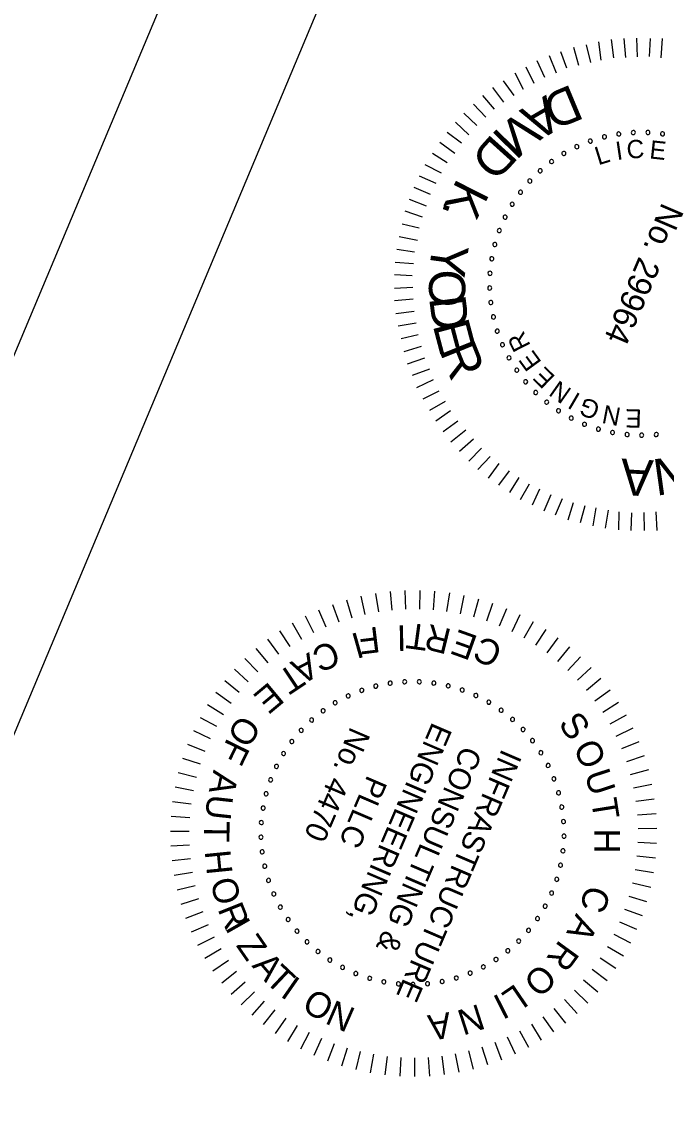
# Model space of a CAD drawing. Extents: x 1968564 to 1968711, y 796599 to 796794.
# Drawn here: x 1968580.42 to 1968589.2, y 796662.05 to 796676.76 of the extents above; entities that cross this region are included whole.
import ezdxf

# ---------------------------------------------------------------- set-up
doc = ezdxf.new("R2010")
doc.units = 0
for name, color, linetype in [('BR_BORDER LINES', 7, 'Continuous'), ('BR_TEXT', 7, 'Continuous'), ('Level 31', 7, 'Continuous')]:
    doc.layers.add(name, color=color, linetype=linetype)

msp = doc.modelspace()

# ---------------------------------------------------------------- linework, layer by layer
at = {"layer": 'BR_BORDER LINES'}
msp.add_line((1968618.549, 796758.212), (1968566.464, 796634.028), dxfattribs=at)
at = {"layer": 'BR_TEXT'}
for p, q in [((1968588.484, 796676.263), (1968588.452, 796676.511)), ((1968588.647, 796676.267), (1968588.626, 796676.523)), ((1968588.806, 796676.274), (1968588.796, 796676.528)), ((1968588.969, 796676.278), (1968588.982, 796676.527)), ((1968589.13, 796676.262), (1968589.148, 796676.523)), ((1968587.843, 796676.119), (1968587.761, 796676.345)), ((1968588.006, 796676.158), (1968587.939, 796676.403)), ((1968588.169, 796676.199), (1968588.112, 796676.441)), ((1968588.31, 796676.232), (1968588.279, 796676.481)), ((1968587.546, 796675.993), (1968587.442, 796676.22)), ((1968587.703, 796676.052), (1968587.606, 796676.288)), ((1968587.253, 796675.831), (1968587.138, 796676.052)), ((1968587.4, 796675.913), (1968587.29, 796676.136)), ((1968587.125, 796675.751), (1968586.982, 796675.947)), ((1968586.988, 796675.657), (1968586.838, 796675.856)), ((1968586.74, 796675.453), (1968586.572, 796675.63)), ((1968586.861, 796675.562), (1968586.698, 796675.748)), ((1968586.616, 796675.339), (1968586.441, 796675.507)), ((1968586.509, 796675.212), (1968586.33, 796675.386)), ((1968586.408, 796675.099), (1968586.212, 796675.243)), ((1968586.318, 796674.958), (1968586.114, 796675.109)), ((1968586.215, 796674.831), (1968586.015, 796674.957)), ((1968586.137, 796674.692), (1968585.916, 796674.806)), ((1968586.065, 796674.551), (1968585.838, 796674.649)), ((1968585.989, 796674.401), (1968585.765, 796674.497)), ((1968585.932, 796674.242), (1968585.702, 796674.333)), ((1968585.878, 796674.09), (1968585.644, 796674.172)), ((1968585.833, 796673.941), (1968585.602, 796673.995)), ((1968585.81, 796673.775), (1968585.561, 796673.822)), ((1968585.771, 796673.613), (1968585.529, 796673.65)), ((1968585.757, 796673.458), (1968585.508, 796673.472)), ((1968585.738, 796673.294), (1968585.496, 796673.305)), ((1968585.745, 796673.135), (1968585.496, 796673.122)), ((1968585.751, 796672.975), (1968585.497, 796672.95)), ((1968585.764, 796672.805), (1968585.515, 796672.774)), ((1968585.793, 796672.647), (1968585.548, 796672.607)), ((1968585.819, 796672.49), (1968585.586, 796672.434)), ((1968585.862, 796672.33), (1968585.625, 796672.256)), ((1968585.907, 796672.172), (1968585.669, 796672.088)), ((1968585.973, 796672.021), (1968585.738, 796671.935)), ((1968586.023, 796671.876), (1968585.797, 796671.768)), ((1968586.102, 796671.723), (1968585.884, 796671.615)), ((1968586.187, 796671.581), (1968585.975, 796671.46)), ((1968586.259, 796671.453), (1968586.06, 796671.311)), ((1968586.36, 796671.313), (1968586.159, 796671.168)), ((1968586.467, 796671.189), (1968586.266, 796671.025)), ((1968586.571, 796671.066), (1968586.381, 796670.901)), ((1968586.68, 796670.944), (1968586.511, 796670.77)), ((1968586.8, 796670.833), (1968586.63, 796670.655)), ((1968586.919, 796670.737), (1968586.771, 796670.539)), ((1968587.06, 796670.639), (1968586.915, 796670.44)), ((1968587.192, 796670.545), (1968587.064, 796670.342)), ((1968587.333, 796670.455), (1968587.208, 796670.243)), ((1968587.472, 796670.388), (1968587.371, 796670.17)), ((1968587.626, 796670.311), (1968587.529, 796670.087)), ((1968587.781, 796670.255), (1968587.686, 796670.034)), ((1968587.929, 796670.199), (1968587.858, 796669.964)), ((1968588.091, 796670.159), (1968588.026, 796669.93)), ((1968588.237, 796670.134), (1968588.199, 796669.889)), ((1968588.405, 796670.099), (1968588.364, 796669.855)), ((1968588.554, 796670.08), (1968588.545, 796669.834)), ((1968588.724, 796670.067), (1968588.713, 796669.825)), ((1968588.893, 796670.069), (1968588.895, 796669.822)), ((1968589.057, 796670.077), (1968589.067, 796669.823)), ((1968585.438, 796668.993), (1968585.463, 796668.74)), ((1968585.64, 796669.006), (1968585.649, 796668.752)), ((1968585.842, 796669.007), (1968585.836, 796668.753)), ((1968586.043, 796668.996), (1968586.022, 796668.742)), ((1968584.844, 796668.88), (1968584.915, 796668.635)), ((1968585.04, 796668.93), (1968585.095, 796668.681)), ((1968585.238, 796668.967), (1968585.278, 796668.716)), ((1968586.244, 796668.973), (1968586.207, 796668.721)), ((1968586.443, 796668.937), (1968586.39, 796668.688)), ((1968586.639, 796668.889), (1968586.571, 796668.643)), ((1968584.463, 796668.745), (1968584.563, 796668.511)), ((1968584.652, 796668.818), (1968584.737, 796668.578)), ((1968586.832, 796668.829), (1968586.749, 796668.588)), ((1968587.021, 796668.758), (1968586.924, 796668.523)), ((1968584.102, 796668.565), (1968584.23, 796668.344)), ((1968584.28, 796668.66), (1968584.394, 796668.433)), ((1968587.205, 796668.675), (1968587.094, 796668.446)), ((1968587.384, 796668.582), (1968587.259, 796668.36)), ((1968583.93, 796668.458), (1968584.071, 796668.246)), ((1968587.557, 796668.477), (1968587.418, 796668.263)), ((1968583.766, 796668.342), (1968583.919, 796668.139)), ((1968587.723, 796668.362), (1968587.572, 796668.157)), ((1968583.608, 796668.216), (1968583.774, 796668.022)), ((1968587.881, 796668.238), (1968587.718, 796668.042)), ((1968583.459, 796668.08), (1968583.636, 796667.897)), ((1968588.032, 796668.103), (1968587.858, 796667.918)), ((1968583.318, 796667.935), (1968583.506, 796667.763)), ((1968588.175, 796667.96), (1968587.989, 796667.786)), ((1968583.186, 796667.782), (1968583.384, 796667.622)), ((1968588.308, 796667.809), (1968588.112, 796667.646)), ((1968583.063, 796667.622), (1968583.271, 796667.474)), ((1968588.432, 796667.649), (1968588.227, 796667.499)), ((1968582.951, 796667.454), (1968583.167, 796667.319)), ((1968588.546, 796667.483), (1968588.332, 796667.345)), ((1968582.849, 796667.279), (1968583.073, 796667.158)), ((1968588.65, 796667.309), (1968588.428, 796667.185)), ((1968582.758, 796667.099), (1968582.989, 796666.992)), ((1968588.743, 796667.13), (1968588.513, 796667.02)), ((1968588.825, 796666.945), (1968588.589, 796666.849)), ((1968582.678, 796666.914), (1968582.915, 796666.82)), ((1968582.61, 796666.724), (1968582.852, 796666.645)), ((1968588.895, 796666.756), (1968588.654, 796666.674)), ((1968582.553, 796666.53), (1968582.8, 796666.466)), ((1968588.954, 796666.563), (1968588.708, 796666.496)), ((1968589, 796666.366), (1968588.751, 796666.315)), ((1968582.509, 796666.333), (1968582.759, 796666.284)), ((1968582.476, 796666.134), (1968582.728, 796666.1)), ((1968589.035, 796666.167), (1968588.783, 796666.131)), ((1968582.455, 796665.933), (1968582.709, 796665.915)), ((1968589.058, 796665.967), (1968588.804, 796665.946)), ((1968589.068, 796665.765), (1968588.813, 796665.76)), ((1968582.447, 796665.731), (1968582.702, 796665.729)), ((1968582.451, 796665.529), (1968582.706, 796665.542)), ((1968589.066, 796665.563), (1968588.811, 796665.573)), ((1968582.468, 796665.328), (1968582.721, 796665.357)), ((1968589.052, 796665.362), (1968588.798, 796665.387)), ((1968582.496, 796665.128), (1968582.747, 796665.172)), ((1968589.025, 796665.162), (1968588.774, 796665.203)), ((1968588.986, 796664.963), (1968588.738, 796665.02)), ((1968582.537, 796664.93), (1968582.785, 796664.99)), ((1968582.59, 796664.735), (1968582.834, 796664.81)), ((1968588.935, 796664.768), (1968588.691, 796664.839)), ((1968582.654, 796664.544), (1968582.893, 796664.633)), ((1968588.873, 796664.576), (1968588.633, 796664.662)), ((1968582.731, 796664.357), (1968582.963, 796664.46)), ((1968588.799, 796664.388), (1968588.565, 796664.489)), ((1968582.818, 796664.175), (1968583.044, 796664.292)), ((1968588.713, 796664.205), (1968588.486, 796664.32)), ((1968588.617, 796664.028), (1968588.397, 796664.156)), ((1968582.916, 796663.998), (1968583.135, 796664.129)), ((1968588.51, 796663.857), (1968588.298, 796663.998)), ((1968583.025, 796663.828), (1968583.235, 796663.972)), ((1968588.392, 796663.692), (1968588.189, 796663.846)), ((1968583.144, 796663.665), (1968583.345, 796663.822)), ((1968588.265, 796663.535), (1968588.072, 796663.702)), ((1968583.273, 796663.51), (1968583.464, 796663.678)), ((1968588.129, 796663.387), (1968587.946, 796663.564)), ((1968583.411, 796663.362), (1968583.591, 796663.542)), ((1968583.558, 796663.224), (1968583.727, 796663.414)), ((1968587.983, 796663.246), (1968587.812, 796663.435)), ((1968583.713, 796663.094), (1968583.87, 796663.295)), ((1968587.83, 796663.115), (1968587.67, 796663.314)), ((1968583.875, 796662.974), (1968584.02, 796663.184)), ((1968587.668, 796662.994), (1968587.521, 796663.202)), ((1968584.045, 796662.864), (1968584.176, 796663.083)), ((1968584.221, 796662.765), (1968584.339, 796662.991)), ((1968587.325, 796662.781), (1968587.204, 796663.005)), ((1968587.5, 796662.882), (1968587.366, 796663.099)), ((1968584.402, 796662.677), (1968584.506, 796662.91)), ((1968584.589, 796662.6), (1968584.678, 796662.838)), ((1968586.959, 796662.612), (1968586.866, 796662.849)), ((1968587.145, 796662.691), (1968587.038, 796662.922)), ((1968584.78, 796662.535), (1968584.855, 796662.778)), ((1968584.974, 796662.481), (1968585.034, 796662.728)), ((1968585.172, 796662.439), (1968585.217, 796662.69)), ((1968586.178, 796662.414), (1968586.145, 796662.666)), ((1968586.377, 796662.445), (1968586.329, 796662.695)), ((1968586.574, 796662.489), (1968586.511, 796662.736)), ((1968586.768, 796662.545), (1968586.69, 796662.787)), ((1968585.372, 796662.409), (1968585.401, 796662.662)), ((1968585.573, 796662.392), (1968585.587, 796662.646)), ((1968585.775, 796662.387), (1968585.773, 796662.641)), ((1968585.977, 796662.394), (1968585.96, 796662.648))]:
    msp.add_line(p, q, dxfattribs=at)
for centre, start, end in [((1968588.355, 796675.186), 14.1575, 194.1575), ((1968588.355, 796675.186), 194.1575, 14.1575), ((1968588.55, 796675.225), 8.619, 188.619), ((1968588.55, 796675.225), 188.619, 8.619), ((1968588.749, 796675.244), 3.0805, 183.0805), ((1968588.749, 796675.244), 183.0805, 3.0805), ((1968588.948, 796675.245), 357.5421, 177.5421), ((1968588.948, 796675.245), 177.5421, 357.5421), ((1968589.147, 796675.227), 352.0036, 172.0036), ((1968589.147, 796675.227), 172.0036, 352.0036), ((1968587.98, 796675.052), 25.2344, 205.2344), ((1968587.98, 796675.052), 205.2344, 25.2344), ((1968588.164, 796675.128), 19.6959, 199.6959), ((1968588.164, 796675.128), 199.6959, 19.6959), ((1968587.637, 796674.849), 36.3113, 216.3113), ((1968587.804, 796674.959), 30.7728, 210.7728), ((1968587.804, 796674.959), 210.7728, 30.7728), ((1968587.482, 796674.724), 41.8498, 221.8498), ((1968587.482, 796674.724), 221.8498, 41.8498), ((1968587.637, 796674.849), 216.3113, 36.3113), ((1968587.34, 796674.584), 47.3882, 227.3882), ((1968587.34, 796674.584), 227.3882, 47.3882), ((1968587.212, 796674.431), 52.9267, 232.9267), ((1968587.212, 796674.431), 232.9267, 52.9267), ((1968587.1, 796674.267), 58.4652, 238.4652), ((1968587.1, 796674.267), 238.4652, 58.4652), ((1968587.003, 796674.092), 64.0036, 244.0036), ((1968587.003, 796674.092), 244.0036, 64.0036), ((1968586.924, 796673.909), 69.5421, 249.5421), ((1968586.924, 796673.909), 249.5421, 69.5421), ((1968586.863, 796673.719), 75.0805, 255.0805), ((1968586.863, 796673.719), 255.0805, 75.0805), ((1968586.821, 796673.525), 80.619, 260.619), ((1968586.821, 796673.525), 260.619, 80.619), ((1968586.798, 796673.327), 86.1575, 266.1575), ((1968586.798, 796673.327), 266.1575, 86.1575), ((1968586.794, 796673.127), 91.6959, 271.6959), ((1968586.794, 796673.127), 271.6959, 91.6959), ((1968586.809, 796672.929), 97.2344, 277.2344), ((1968586.809, 796672.929), 277.2344, 97.2344), ((1968586.843, 796672.732), 102.7728, 282.7728), ((1968586.843, 796672.732), 282.7728, 102.7728), ((1968586.896, 796672.54), 108.3113, 288.3113), ((1968586.896, 796672.54), 288.3113, 108.3113), ((1968586.967, 796672.354), 113.8498, 293.8498), ((1968586.967, 796672.354), 293.8498, 113.8498), ((1968587.056, 796672.176), 119.3882, 299.3882), ((1968587.056, 796672.176), 299.3882, 119.3882), ((1968587.162, 796672.007), 124.9267, 304.9267), ((1968587.162, 796672.007), 304.9267, 124.9267), ((1968587.283, 796671.849), 130.4652, 310.4652), ((1968587.283, 796671.849), 310.4652, 130.4652), ((1968587.42, 796671.703), 136.0036, 316.0036), ((1968587.42, 796671.703), 316.0036, 136.0036), ((1968587.569, 796671.572), 141.5421, 321.5421), ((1968587.569, 796671.572), 321.5421, 141.5421), ((1968587.731, 796671.455), 147.0805, 327.0805), ((1968587.731, 796671.455), 327.0805, 147.0805), ((1968587.903, 796671.355), 152.619, 332.619), ((1968587.903, 796671.355), 332.619, 152.619), ((1968588.084, 796671.271), 158.1575, 338.1575), ((1968588.084, 796671.271), 338.1575, 158.1575), ((1968588.273, 796671.206), 163.6959, 343.6959), ((1968588.273, 796671.206), 343.6959, 163.6959), ((1968588.466, 796671.159), 169.2344, 349.2344), ((1968588.466, 796671.159), 349.2344, 169.2344), ((1968588.664, 796671.131), 174.7728, 354.7728), ((1968588.664, 796671.131), 354.7728, 174.7728), ((1968588.863, 796671.122), 0.3113, 180.3113), ((1968588.863, 796671.122), 180.3113, 0.3113), ((1968589.062, 796671.132), 5.8498, 185.8498), ((1968589.062, 796671.132), 185.8498, 5.8498), ((1968585.051, 796667.647), 19.6959, 199.6959), ((1968585.242, 796667.705), 14.1575, 194.1575), ((1968585.242, 796667.705), 194.1575, 14.1575), ((1968585.437, 796667.744), 8.619, 188.619), ((1968585.437, 796667.744), 188.619, 8.619), ((1968585.635, 796667.764), 3.0805, 183.0805), ((1968585.635, 796667.764), 183.0805, 3.0805), ((1968585.835, 796667.764), 357.5421, 177.5421), ((1968585.835, 796667.764), 177.5421, 357.5421), ((1968586.033, 796667.746), 172.0036, 352.0036), ((1968586.033, 796667.746), 352.0036, 172.0036), ((1968586.229, 796667.708), 166.4652, 346.4652), ((1968586.229, 796667.708), 346.4652, 166.4652), ((1968586.42, 796667.652), 340.9267, 160.9267), ((1968584.867, 796667.571), 25.2344, 205.2344), ((1968584.867, 796667.571), 205.2344, 25.2344), ((1968585.051, 796667.647), 199.6959, 19.6959), ((1968586.42, 796667.652), 160.9267, 340.9267), ((1968586.605, 796667.577), 155.3882, 335.3882), ((1968586.605, 796667.577), 335.3882, 155.3882), ((1968584.524, 796667.368), 36.3113, 216.3113), ((1968584.524, 796667.368), 216.3113, 36.3113), ((1968584.69, 796667.478), 30.7728, 210.7728), ((1968584.69, 796667.478), 210.7728, 30.7728), ((1968586.782, 796667.485), 149.8498, 329.8498), ((1968586.782, 796667.485), 329.8498, 149.8498), ((1968586.949, 796667.377), 144.3113, 324.3113), ((1968586.949, 796667.377), 324.3113, 144.3113), ((1968584.369, 796667.243), 41.8498, 221.8498), ((1968584.369, 796667.243), 221.8498, 41.8498), ((1968587.105, 796667.252), 138.7728, 318.7728), ((1968587.105, 796667.252), 318.7728, 138.7728), ((1968584.227, 796667.103), 47.3882, 227.3882), ((1968584.227, 796667.103), 227.3882, 47.3882), ((1968587.248, 796667.114), 133.2344, 313.2344), ((1968587.248, 796667.114), 313.2344, 133.2344), ((1968584.099, 796666.95), 52.9267, 232.9267), ((1968584.099, 796666.95), 232.9267, 52.9267), ((1968587.377, 796666.962), 127.6959, 307.6959), ((1968587.377, 796666.962), 307.6959, 127.6959), ((1968583.986, 796666.786), 58.4652, 238.4652), ((1968583.986, 796666.786), 238.4652, 58.4652), ((1968587.491, 796666.798), 122.1575, 302.1575), ((1968587.491, 796666.798), 302.1575, 122.1575), ((1968583.89, 796666.611), 64.0036, 244.0036), ((1968587.588, 796666.624), 116.619, 296.619), ((1968587.588, 796666.624), 296.619, 116.619), ((1968583.89, 796666.611), 244.0036, 64.0036), ((1968583.811, 796666.428), 69.5421, 249.5421), ((1968583.811, 796666.428), 249.5421, 69.5421), ((1968587.668, 796666.442), 111.0805, 291.0805), ((1968587.668, 796666.442), 291.0805, 111.0805), ((1968583.75, 796666.239), 75.0805, 255.0805), ((1968583.75, 796666.239), 255.0805, 75.0805), ((1968587.731, 796666.252), 105.5421, 285.5421), ((1968587.731, 796666.252), 285.5421, 105.5421), ((1968583.708, 796666.044), 80.619, 260.619), ((1968583.708, 796666.044), 260.619, 80.619), ((1968587.774, 796666.058), 100.0036, 280.0036), ((1968587.774, 796666.058), 280.0036, 100.0036), ((1968583.684, 796665.846), 86.1575, 266.1575), ((1968583.684, 796665.846), 266.1575, 86.1575), ((1968587.799, 796665.86), 94.4652, 274.4652), ((1968587.799, 796665.86), 274.4652, 94.4652), ((1968583.68, 796665.647), 91.6959, 271.6959), ((1968583.68, 796665.647), 271.6959, 91.6959), ((1968587.805, 796665.661), 88.9267, 268.9267), ((1968587.805, 796665.661), 268.9267, 88.9267), ((1968583.695, 796665.448), 97.2344, 277.2344), ((1968583.695, 796665.448), 277.2344, 97.2344), ((1968587.791, 796665.462), 83.3882, 263.3882), ((1968587.791, 796665.462), 263.3882, 83.3882), ((1968583.73, 796665.251), 102.7728, 282.7728), ((1968583.73, 796665.251), 282.7728, 102.7728), ((1968587.758, 796665.265), 77.8498, 257.8498), ((1968587.758, 796665.265), 257.8498, 77.8498), ((1968583.783, 796665.059), 108.3113, 288.3113), ((1968583.783, 796665.059), 288.3113, 108.3113), ((1968587.706, 796665.073), 72.3113, 252.3113), ((1968587.706, 796665.073), 252.3113, 72.3113), ((1968583.854, 796664.873), 113.8498, 293.8498), ((1968583.854, 796664.873), 293.8498, 113.8498), ((1968587.636, 796664.886), 66.7728, 246.7728), ((1968587.636, 796664.886), 246.7728, 66.7728), ((1968587.549, 796664.707), 61.2344, 241.2344), ((1968587.549, 796664.707), 241.2344, 61.2344), ((1968583.943, 796664.695), 119.3882, 299.3882), ((1968583.943, 796664.695), 299.3882, 119.3882), ((1968584.049, 796664.526), 124.9267, 304.9267), ((1968584.049, 796664.526), 304.9267, 124.9267), ((1968587.444, 796664.538), 55.6959, 235.6959), ((1968587.444, 796664.538), 235.6959, 55.6959), ((1968584.17, 796664.368), 130.4652, 310.4652), ((1968584.17, 796664.368), 310.4652, 130.4652), ((1968587.323, 796664.379), 50.1575, 230.1575), ((1968587.323, 796664.379), 230.1575, 50.1575), ((1968584.306, 796664.222), 136.0036, 316.0036), ((1968584.306, 796664.222), 316.0036, 136.0036), ((1968587.188, 796664.232), 44.619, 224.619), ((1968587.188, 796664.232), 224.619, 44.619), ((1968584.456, 796664.091), 141.5421, 321.5421), ((1968584.456, 796664.091), 321.5421, 141.5421), ((1968584.618, 796663.974), 327.0805, 147.0805), ((1968586.879, 796663.982), 33.5421, 213.5421), ((1968586.879, 796663.982), 213.5421, 33.5421), ((1968587.04, 796664.1), 39.0805, 219.0805), ((1968587.04, 796664.1), 219.0805, 39.0805), ((1968584.618, 796663.974), 147.0805, 327.0805), ((1968584.79, 796663.874), 152.619, 332.619), ((1968584.79, 796663.874), 332.619, 152.619), ((1968586.707, 796663.88), 28.0036, 208.0036), ((1968586.707, 796663.88), 208.0036, 28.0036), ((1968584.971, 796663.79), 158.1575, 338.1575), ((1968584.971, 796663.79), 338.1575, 158.1575), ((1968585.159, 796663.725), 163.6959, 343.6959), ((1968585.159, 796663.725), 343.6959, 163.6959), ((1968585.353, 796663.678), 349.2344, 169.2344), ((1968586.146, 796663.681), 11.3882, 191.3882), ((1968586.339, 796663.729), 16.9267, 196.9267), ((1968586.339, 796663.729), 196.9267, 16.9267), ((1968586.527, 796663.796), 22.4652, 202.4652), ((1968586.527, 796663.796), 202.4652, 22.4652), ((1968585.353, 796663.678), 169.2344, 349.2344), ((1968585.55, 796663.65), 354.7728, 174.7728), ((1968585.55, 796663.65), 174.7728, 354.7728), ((1968585.749, 796663.641), 0.3113, 180.3113), ((1968585.749, 796663.641), 180.3113, 0.3113), ((1968585.948, 796663.651), 5.8498, 185.8498), ((1968585.948, 796663.651), 185.8498, 5.8498), ((1968586.146, 796663.681), 191.3882, 11.3882)]:
    msp.add_arc(centre, 0.028, start, end, dxfattribs=at)
at = {"layer": 'Level 31'}
msp.add_lwpolyline([(1968619.541, 796765.748), (1968563.846, 796632.955), (1968644.997, 796598.919), (1968700.693, 796731.712)], close=True, dxfattribs=at)

# ---------------------------------------------------------------- texts
at = {"layer": 'BR_TEXT'}
for s, height, rotation, p in [('A', 0.494, 210.0837, (1968587.565, 796675.761)), ('D', 0.494, 202.6513, (1968587.91, 796675.906)), ('V', 0.494, 217.7639, (1968587.231, 796675.567)), ('D', 0.494, 228.0455, (1968586.83, 796675.24)), ('I', 0.494, 225.4441, (1968586.926, 796675.33)), ('L', 0.249, 17.2055, (1968588.272, 796674.797)), ('I', 0.249, 8.3471, (1968588.527, 796674.867)), ('C', 0.249, 3.6726, (1968588.665, 796674.887)), ('E', 0.249, 353.7815, (1968588.961, 796674.893)), ('K', 0.494, 243.344, (1968586.357, 796674.635)), ('.', 0.494, 250.4048, (1968586.196, 796674.318)), ('No. 29964', 0.327, 246.7728, (1968589.144, 796674.304)), ('Y', 0.494, 262.1109, (1968586.02, 796673.756)), ('O', 0.494, 269.6673, (1968585.968, 796673.38)), ('D', 0.494, 277.3475, (1968585.967, 796672.993)), ('E', 0.494, 284.7799, (1968586.015, 796672.622)), ('R', 0.249, 117.028, (1968587.355, 796672.343)), ('R', 0.494, 291.8408, (1968586.104, 796672.278)), ('E', 0.249, 126.2304, (1968587.508, 796672.115)), ('E', 0.249, 135.4327, (1968587.697, 796671.915)), ('N', 0.249, 144.9799, (1968587.923, 796671.741)), ('I', 0.249, 149.6544, (1968588.044, 796671.671)), ('G', 0.249, 159.5455, (1968588.315, 796671.556)), ('N', 0.249, 169.0926, (1968588.593, 796671.49)), ('E', 0.249, 178.295, (1968588.867, 796671.471)), ('A', 0.496, 176.7252, (1968589.031, 796670.78)), ('N', 0.496, 187.9497, (1968589.466, 796670.854)), ('T', 0.349, 172.2711, (1968585.971, 796668.531)), ('I', 0.349, 195.7728, (1968585.01, 796668.444)), ('F', 0.349, 187.0173, (1968585.274, 796668.516)), ('I', 0.349, 181.0173, (1968585.655, 796668.535)), ('R', 0.349, 166.2711, (1968586.289, 796668.474)), ('E', 0.349, 160.2711, (1968586.649, 796668.378)), ('C', 0.349, 201.7728, (1968584.66, 796668.334)), ('C', 0.349, 154.2711, (1968586.993, 796668.253)), ('A', 0.349, 207.7728, (1968584.337, 796668.169)), ('T', 0.349, 213.7728, (1968584.111, 796668.028)), ('E', 0.349, 219.7728, (1968583.797, 796667.775)), ('O', 0.349, 237.7728, (1968583.4, 796667.334)), ('S', 0.349, 306.1543, (1968587.718, 796667.189)), ('No. 4470', 0.2991, 246.7728, (1968584.901, 796667.163)), ('ENGINEERING,', 0.29909, 246.7728, (1968586.014, 796667.226)), ('F', 0.349, 243.7728, (1968583.225, 796667.011)), ('O', 0.349, 297.1243, (1968587.921, 796666.864)), ('CONSULTING &', 0.29909, 246.7728, (1968586.424, 796666.908)), ('INFRASTRUCTURE', 0.29909, 246.7728, (1968586.963, 796666.862)), ('A', 0.349, 257.7728, (1968583.034, 796666.571)), ('U', 0.349, 288.0942, (1968588.079, 796666.507)), ('PLLC', 0.2991, 246.7728, (1968585.131, 796666.504)), ('U', 0.349, 263.7728, (1968582.954, 796666.24)), ('T', 0.349, 279.0642, (1968588.173, 796666.15)), ('T', 0.349, 269.7728, (1968582.902, 796665.864)), ('H', 0.349, 270.0342, (1968588.217, 796665.763)), ('H', 0.349, 275.7728, (1968582.912, 796665.456)), ('O', 0.349, 285.7728, (1968582.982, 796665.044)), ('C', 0.349, 251.9741, (1968588.117, 796665.012)), ('R', 0.349, 291.7728, (1968583.085, 796664.669)), ('A', 0.349, 242.9441, (1968587.973, 796664.619)), ('I', 0.349, 299.5799, (1968583.183, 796664.414)), ('Z', 0.349, 304.6414, (1968583.332, 796664.173)), ('R', 0.349, 233.9141, (1968587.749, 796664.261)), ('A', 0.349, 310.6414, (1968583.546, 796663.893)), ('T', 0.349, 316.6414, (1968583.721, 796663.686)), ('O', 0.349, 224.8841, (1968587.488, 796663.947)), ('I', 0.349, 325.1553, (1968583.93, 796663.487)), ('O', 0.349, 330.4545, (1968584.217, 796663.299)), ('L', 0.349, 214.354, (1968587.149, 796663.66)), ('N', 0.349, 336.4545, (1968584.537, 796663.117)), ('I', 0.349, 206.824, (1968586.928, 796663.525)), ('A', 0.349, 188.764, (1968586.242, 796663.266)), ('N', 0.349, 197.794, (1968586.647, 796663.379))]:
    msp.add_text(s, height=height, rotation=rotation, dxfattribs=at).set_placement(p)

doc.saveas('drawing.dxf')
